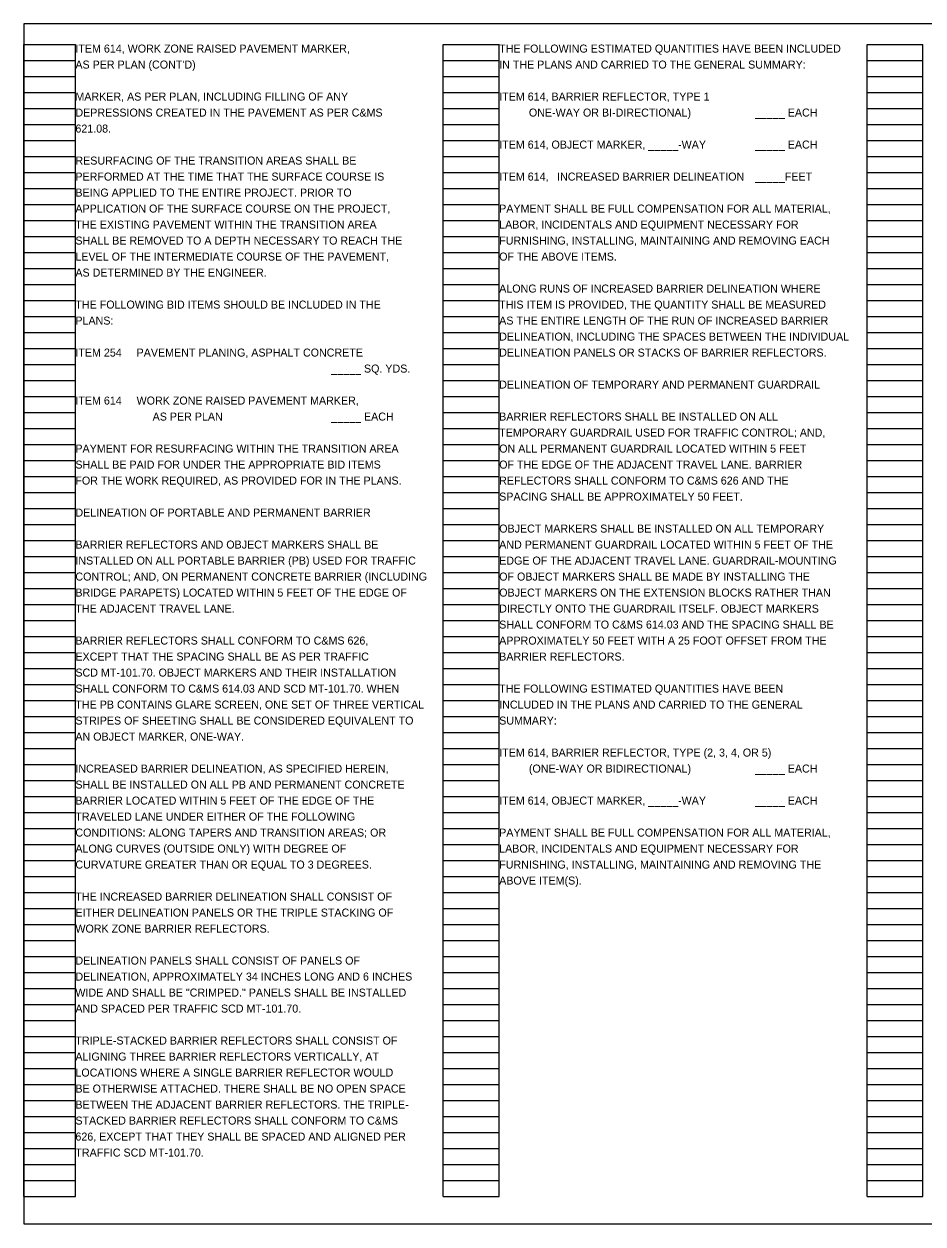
# Model space of a CAD drawing. Extents: x -34 to 2132911, y 0 to 658646.
# Drawn here: x 103.5 to 119.24, y 0.5 to 21.5 of the extents above; entities that cross this region are included whole.
import ezdxf

# ---------------------------------------------------------------- set-up
doc = ezdxf.new("R2010")
doc.units = 0
for name, color, linetype in [('SC_Scratch1', 7, 'Continuous'), ('SH_Data', 7, 'Continuous'), ('SH_Text', 7, 'Continuous')]:
    doc.layers.add(name, color=color, linetype=linetype)

msp = doc.modelspace()

# ---------------------------------------------------------------- linework, layer by layer
at = {"layer": 'SC_Scratch1'}
msp.add_lwpolyline([(103.5, 0.5), (134, 0.5), (134, 21.5), (103.5, 21.5)], close=True, dxfattribs=at)
at = {"layer": 'SH_Data'}
for p, q in [((103.5, 0.98), (103.5, 21.14)), ((103.5, 21.14), (104.4, 21.14)), ((104.4, 0.98), (104.4, 21.14)), ((110.84, 0.98), (110.84, 21.14)), ((110.84, 21.14), (111.82, 21.14)), ((111.82, 0.98), (111.82, 21.14)), ((118.26, 0.98), (118.26, 21.14)), ((118.26, 21.14), (119.24, 21.14)), ((119.24, 0.98), (119.24, 21.14)), ((103.5, 20.86), (104.4, 20.86)), ((110.84, 20.86), (111.82, 20.86)), ((118.26, 20.86), (119.24, 20.86)), ((103.5, 20.58), (104.4, 20.58)), ((110.84, 20.58), (111.82, 20.58)), ((118.26, 20.58), (119.24, 20.58)), ((103.5, 20.3), (104.4, 20.3)), ((110.84, 20.3), (111.82, 20.3)), ((118.26, 20.3), (119.24, 20.3)), ((103.5, 20.02), (104.4, 20.02)), ((110.84, 20.02), (111.82, 20.02)), ((118.26, 20.02), (119.24, 20.02)), ((103.5, 19.74), (104.4, 19.74)), ((110.84, 19.74), (111.82, 19.74)), ((118.26, 19.74), (119.24, 19.74)), ((103.5, 19.46), (104.4, 19.46)), ((110.84, 19.46), (111.82, 19.46)), ((118.26, 19.46), (119.24, 19.46)), ((103.5, 19.18), (104.4, 19.18)), ((110.84, 19.18), (111.82, 19.18)), ((118.26, 19.18), (119.24, 19.18)), ((103.5, 18.9), (104.4, 18.9)), ((110.84, 18.9), (111.82, 18.9)), ((118.26, 18.9), (119.24, 18.9)), ((103.5, 18.62), (104.4, 18.62)), ((110.84, 18.62), (111.82, 18.62)), ((118.26, 18.62), (119.24, 18.62)), ((103.5, 18.34), (104.4, 18.34)), ((110.84, 18.34), (111.82, 18.34)), ((118.26, 18.34), (119.24, 18.34)), ((103.5, 18.06), (104.4, 18.06)), ((110.84, 18.06), (111.82, 18.06)), ((118.26, 18.06), (119.24, 18.06)), ((103.5, 17.78), (104.4, 17.78)), ((110.84, 17.78), (111.82, 17.78)), ((118.26, 17.78), (119.24, 17.78)), ((103.5, 17.5), (104.4, 17.5)), ((110.84, 17.5), (111.82, 17.5)), ((118.26, 17.5), (119.24, 17.5)), ((103.5, 17.22), (104.4, 17.22)), ((110.84, 17.22), (111.82, 17.22)), ((118.26, 17.22), (119.24, 17.22)), ((103.5, 16.94), (104.4, 16.94)), ((110.84, 16.94), (111.82, 16.94)), ((118.26, 16.94), (119.24, 16.94)), ((103.5, 16.66), (104.4, 16.66)), ((110.84, 16.66), (111.82, 16.66)), ((118.26, 16.66), (119.24, 16.66)), ((103.5, 16.38), (104.4, 16.38)), ((110.84, 16.38), (111.82, 16.38)), ((118.26, 16.38), (119.24, 16.38)), ((103.5, 16.1), (104.4, 16.1)), ((110.84, 16.1), (111.82, 16.1)), ((118.26, 16.1), (119.24, 16.1)), ((103.5, 15.82), (104.4, 15.82)), ((110.84, 15.82), (111.82, 15.82)), ((118.26, 15.82), (119.24, 15.82)), ((103.5, 15.54), (104.4, 15.54)), ((110.84, 15.54), (111.82, 15.54)), ((118.26, 15.54), (119.24, 15.54)), ((103.5, 15.26), (104.4, 15.26)), ((110.84, 15.26), (111.82, 15.26)), ((118.26, 15.26), (119.24, 15.26)), ((103.5, 14.98), (104.4, 14.98)), ((110.84, 14.98), (111.82, 14.98)), ((118.26, 14.98), (119.24, 14.98)), ((103.5, 14.7), (104.4, 14.7)), ((110.84, 14.7), (111.82, 14.7)), ((118.26, 14.7), (119.24, 14.7)), ((103.5, 14.42), (104.4, 14.42)), ((110.84, 14.42), (111.82, 14.42)), ((118.26, 14.42), (119.24, 14.42)), ((103.5, 14.14), (104.4, 14.14)), ((110.84, 14.14), (111.82, 14.14)), ((118.26, 14.14), (119.24, 14.14)), ((103.5, 13.86), (104.4, 13.86)), ((110.84, 13.86), (111.82, 13.86)), ((118.26, 13.86), (119.24, 13.86)), ((103.5, 13.58), (104.4, 13.58)), ((110.84, 13.58), (111.82, 13.58)), ((118.26, 13.58), (119.24, 13.58)), ((103.5, 13.3), (104.4, 13.3)), ((110.84, 13.3), (111.82, 13.3)), ((118.26, 13.3), (119.24, 13.3)), ((103.5, 13.02), (104.4, 13.02)), ((110.84, 13.02), (111.82, 13.02)), ((118.26, 13.02), (119.24, 13.02)), ((103.5, 12.74), (104.4, 12.74)), ((110.84, 12.74), (111.82, 12.74)), ((118.26, 12.74), (119.24, 12.74)), ((103.5, 12.46), (104.4, 12.46)), ((110.84, 12.46), (111.82, 12.46)), ((118.26, 12.46), (119.24, 12.46)), ((103.5, 12.18), (104.4, 12.18)), ((110.84, 12.18), (111.82, 12.18)), ((118.26, 12.18), (119.24, 12.18)), ((103.5, 11.9), (104.4, 11.9)), ((110.84, 11.9), (111.82, 11.9)), ((118.26, 11.9), (119.24, 11.9)), ((103.5, 11.62), (104.4, 11.62)), ((110.84, 11.62), (111.82, 11.62)), ((118.26, 11.62), (119.24, 11.62)), ((103.5, 11.34), (104.4, 11.34)), ((110.84, 11.34), (111.82, 11.34)), ((118.26, 11.34), (119.24, 11.34)), ((103.5, 11.06), (104.4, 11.06)), ((110.84, 11.06), (111.82, 11.06)), ((118.26, 11.06), (119.24, 11.06)), ((103.5, 10.78), (104.4, 10.78)), ((110.84, 10.78), (111.82, 10.78)), ((118.26, 10.78), (119.24, 10.78)), ((103.5, 10.5), (104.4, 10.5)), ((110.84, 10.5), (111.82, 10.5)), ((118.26, 10.5), (119.24, 10.5)), ((103.5, 10.22), (104.4, 10.22)), ((110.84, 10.22), (111.82, 10.22)), ((118.26, 10.22), (119.24, 10.22)), ((103.5, 9.94), (104.4, 9.94)), ((110.84, 9.94), (111.82, 9.94)), ((118.26, 9.94), (119.24, 9.94)), ((103.5, 9.66), (104.4, 9.66)), ((110.84, 9.66), (111.82, 9.66)), ((118.26, 9.66), (119.24, 9.66)), ((103.5, 9.38), (104.4, 9.38)), ((110.84, 9.38), (111.82, 9.38)), ((118.26, 9.38), (119.24, 9.38)), ((103.5, 9.1), (104.4, 9.1)), ((110.84, 9.1), (111.82, 9.1)), ((118.26, 9.1), (119.24, 9.1)), ((103.5, 8.82), (104.4, 8.82)), ((110.84, 8.82), (111.82, 8.82)), ((118.26, 8.82), (119.24, 8.82)), ((103.5, 8.54), (104.4, 8.54)), ((110.84, 8.54), (111.82, 8.54)), ((118.26, 8.54), (119.24, 8.54)), ((103.5, 8.26), (104.4, 8.26)), ((110.84, 8.26), (111.82, 8.26)), ((118.26, 8.26), (119.24, 8.26)), ((103.5, 7.98), (104.4, 7.98)), ((110.84, 7.98), (111.82, 7.98)), ((118.26, 7.98), (119.24, 7.98)), ((103.5, 7.7), (104.4, 7.7)), ((110.84, 7.7), (111.82, 7.7)), ((118.26, 7.7), (119.24, 7.7)), ((103.5, 7.42), (104.4, 7.42)), ((110.84, 7.42), (111.82, 7.42)), ((118.26, 7.42), (119.24, 7.42)), ((103.5, 7.14), (104.4, 7.14)), ((110.84, 7.14), (111.82, 7.14)), ((118.26, 7.14), (119.24, 7.14)), ((103.5, 6.86), (104.4, 6.86)), ((110.84, 6.86), (111.82, 6.86)), ((118.26, 6.86), (119.24, 6.86)), ((103.5, 6.58), (104.4, 6.58)), ((110.84, 6.58), (111.82, 6.58)), ((118.26, 6.58), (119.24, 6.58)), ((103.5, 6.3), (104.4, 6.3)), ((110.84, 6.3), (111.82, 6.3)), ((118.26, 6.3), (119.24, 6.3)), ((103.5, 6.02), (104.4, 6.02)), ((110.84, 6.02), (111.82, 6.02)), ((118.26, 6.02), (119.24, 6.02)), ((103.5, 5.74), (104.4, 5.74)), ((110.84, 5.74), (111.82, 5.74)), ((118.26, 5.74), (119.24, 5.74)), ((103.5, 5.46), (104.4, 5.46)), ((110.84, 5.46), (111.82, 5.46)), ((118.26, 5.46), (119.24, 5.46)), ((103.5, 5.18), (104.4, 5.18)), ((110.84, 5.18), (111.82, 5.18)), ((118.26, 5.18), (119.24, 5.18)), ((103.5, 4.9), (104.4, 4.9)), ((110.84, 4.9), (111.82, 4.9)), ((118.26, 4.9), (119.24, 4.9)), ((103.5, 4.62), (104.4, 4.62)), ((110.84, 4.62), (111.82, 4.62)), ((118.26, 4.62), (119.24, 4.62)), ((103.5, 4.34), (104.4, 4.34)), ((110.84, 4.34), (111.82, 4.34)), ((118.26, 4.34), (119.24, 4.34)), ((103.5, 4.06), (104.4, 4.06)), ((110.84, 4.06), (111.82, 4.06)), ((118.26, 4.06), (119.24, 4.06)), ((103.5, 3.78), (104.4, 3.78)), ((110.84, 3.78), (111.82, 3.78)), ((118.26, 3.78), (119.24, 3.78)), ((103.5, 3.5), (104.4, 3.5)), ((110.84, 3.5), (111.82, 3.5)), ((118.26, 3.5), (119.24, 3.5)), ((103.5, 3.22), (104.4, 3.22)), ((110.84, 3.22), (111.82, 3.22)), ((118.26, 3.22), (119.24, 3.22)), ((103.5, 2.94), (104.4, 2.94)), ((110.84, 2.94), (111.82, 2.94)), ((118.26, 2.94), (119.24, 2.94)), ((103.5, 2.66), (104.4, 2.66)), ((110.84, 2.66), (111.82, 2.66)), ((118.26, 2.66), (119.24, 2.66)), ((103.5, 2.38), (104.4, 2.38)), ((110.84, 2.38), (111.82, 2.38)), ((118.26, 2.38), (119.24, 2.38)), ((103.5, 2.1), (104.4, 2.1)), ((110.84, 2.1), (111.82, 2.1)), ((118.26, 2.1), (119.24, 2.1)), ((103.5, 1.82), (104.4, 1.82)), ((110.84, 1.82), (111.82, 1.82)), ((118.26, 1.82), (119.24, 1.82)), ((103.5, 1.54), (104.4, 1.54)), ((110.84, 1.54), (111.82, 1.54)), ((118.26, 1.54), (119.24, 1.54)), ((103.5, 1.26), (104.4, 1.26)), ((110.84, 1.26), (111.82, 1.26)), ((118.26, 1.26), (119.24, 1.26)), ((103.5, 0.98), (104.4, 0.98)), ((110.84, 0.98), (111.82, 0.98)), ((118.26, 0.98), (119.24, 0.98))]:
    msp.add_line(p, q, dxfattribs=at)

# ---------------------------------------------------------------- texts
at = {"layer": 'SH_Text'}
for s, p in [('ITEM 614, WORK ZONE RAISED PAVEMENT MARKER,', (104.4, 21)), ('THE FOLLOWING ESTIMATED QUANTITIES HAVE BEEN INCLUDED', (111.82, 21)), ("AS PER PLAN (CONT'D) ", (104.4, 20.72)), ('IN THE PLANS AND CARRIED TO THE GENERAL SUMMARY:', (111.82, 20.72)), ('MARKER, AS PER PLAN, INCLUDING FILLING OF ANY', (104.4, 20.16)), ('ITEM 614, BARRIER REFLECTOR, TYPE 1', (111.82, 20.16)), ('DEPRESSIONS CREATED IN THE PAVEMENT AS PER C&MS', (104.4, 19.88)), ('          ONE-WAY OR BI-DIRECTIONAL)         ', (111.82, 19.88)), ('_____ EACH', (116.3, 19.88)), ('621.08.', (104.4, 19.6)), ('ITEM 614, OBJECT MARKER, _____-WAY     ', (111.82, 19.32)), ('_____ EACH', (116.3, 19.32)), ('RESURFACING OF THE TRANSITION AREAS SHALL BE', (104.4, 19.04)), ('PERFORMED AT THE TIME THAT THE SURFACE COURSE IS', (104.4, 18.76)), ('ITEM 614, ', (111.82, 18.76)), ('INCREASED BARRIER DELINEATION', (112.834, 18.76)), ('_____FEET', (116.3, 18.76)), ('BEING APPLIED TO THE ENTIRE PROJECT. PRIOR TO', (104.4, 18.48)), ('APPLICATION OF THE SURFACE COURSE ON THE PROJECT,', (104.4, 18.2)), ('PAYMENT SHALL BE FULL COMPENSATION FOR ALL MATERIAL,', (111.82, 18.2)), ('THE EXISTING PAVEMENT WITHIN THE TRANSITION AREA', (104.4, 17.92)), ('LABOR, INCIDENTALS AND EQUIPMENT NECESSARY FOR', (111.82, 17.92)), ('SHALL BE REMOVED TO A DEPTH NECESSARY TO REACH THE', (104.4, 17.64)), ('FURNISHING, INSTALLING, MAINTAINING AND REMOVING EACH', (111.82, 17.64)), ('LEVEL OF THE INTERMEDIATE COURSE OF THE PAVEMENT,', (104.4, 17.36)), ('OF THE ABOVE ITEMS.', (111.82, 17.36)), ('AS DETERMINED BY THE ENGINEER.', (104.4, 17.08)), ('ALONG RUNS OF INCREASED BARRIER DELINEATION WHERE', (111.82, 16.8)), ('THE FOLLOWING BID ITEMS SHOULD BE INCLUDED IN THE', (104.4, 16.52)), ('THIS ITEM IS PROVIDED, THE QUANTITY SHALL BE MEASURED', (111.82, 16.52)), ('PLANS:', (104.4, 16.24)), ('AS THE ENTIRE LENGTH OF THE RUN OF INCREASED BARRIER', (111.82, 16.24)), ('DELINEATION, INCLUDING THE SPACES BETWEEN THE INDIVIDUAL', (111.82, 15.96)), ('ITEM 254     PAVEMENT PLANING, ASPHALT CONCRETE', (104.4, 15.68)), ('DELINEATION PANELS OR STACKS OF BARRIER REFLECTORS.', (111.82, 15.68)), ('_____ SQ. YDS.', (108.88, 15.4)), ('DELINEATION OF TEMPORARY AND PERMANENT GUARDRAIL', (111.82, 15.12)), ('ITEM 614     WORK ZONE RAISED PAVEMENT MARKER,', (104.4, 14.84)), ('                          AS PER PLAN     ', (104.4, 14.56)), ('_____ EACH', (108.88, 14.56)), ('BARRIER REFLECTORS SHALL BE INSTALLED ON ALL', (111.82, 14.56)), ('TEMPORARY GUARDRAIL USED FOR TRAFFIC CONTROL; AND,', (111.82, 14.28)), ('PAYMENT FOR RESURFACING WITHIN THE TRANSITION AREA', (104.4, 14)), ('ON ALL PERMANENT GUARDRAIL LOCATED WITHIN 5 FEET', (111.82, 14)), ('SHALL BE PAID FOR UNDER THE APPROPRIATE BID ITEMS', (104.4, 13.72)), ('OF THE EDGE OF THE ADJACENT TRAVEL LANE. BARRIER', (111.82, 13.72)), ('FOR THE WORK REQUIRED, AS PROVIDED FOR IN THE PLANS.', (104.4, 13.44)), ('REFLECTORS SHALL CONFORM TO C&MS 626 AND THE', (111.82, 13.44)), ('SPACING SHALL BE APPROXIMATELY 50 FEET.', (111.82, 13.16)), ('DELINEATION OF PORTABLE AND PERMANENT BARRIER', (104.4, 12.88)), ('OBJECT MARKERS SHALL BE INSTALLED ON ALL TEMPORARY', (111.82, 12.6)), ('BARRIER REFLECTORS AND OBJECT MARKERS SHALL BE', (104.4, 12.32)), ('AND PERMANENT GUARDRAIL LOCATED WITHIN 5 FEET OF THE', (111.82, 12.32)), ('INSTALLED ON ALL PORTABLE BARRIER (PB) USED FOR TRAFFIC', (104.4, 12.04)), ('EDGE OF THE ADJACENT TRAVEL LANE. GUARDRAIL-MOUNTING', (111.82, 12.04)), ('CONTROL; AND, ON PERMANENT CONCRETE BARRIER (INCLUDING', (104.4, 11.76)), ('OF OBJECT MARKERS SHALL BE MADE BY INSTALLING THE', (111.82, 11.76)), ('BRIDGE PARAPETS) LOCATED WITHIN 5 FEET OF THE EDGE OF', (104.4, 11.48)), ('OBJECT MARKERS ON THE EXTENSION BLOCKS RATHER THAN', (111.82, 11.48)), ('THE ADJACENT TRAVEL LANE.', (104.4, 11.2)), ('DIRECTLY ONTO THE GUARDRAIL ITSELF. OBJECT MARKERS', (111.82, 11.2)), ('SHALL CONFORM TO C&MS 614.03 AND THE SPACING SHALL BE', (111.82, 10.92)), ('BARRIER REFLECTORS SHALL CONFORM TO C&MS 626,', (104.4, 10.64)), ('APPROXIMATELY 50 FEET WITH A 25 FOOT OFFSET FROM THE', (111.82, 10.64)), ('EXCEPT THAT THE SPACING SHALL BE AS PER TRAFFIC', (104.4, 10.36)), ('BARRIER REFLECTORS.', (111.82, 10.36)), ('SCD MT-101.70. OBJECT MARKERS AND THEIR INSTALLATION', (104.4, 10.08)), ('SHALL CONFORM TO C&MS 614.03 AND SCD MT-101.70. WHEN', (104.4, 9.8)), ('THE FOLLOWING ESTIMATED QUANTITIES HAVE BEEN', (111.82, 9.8)), ('THE PB CONTAINS GLARE SCREEN, ONE SET OF THREE VERTICAL', (104.4, 9.52)), ('INCLUDED IN THE PLANS AND CARRIED TO THE GENERAL', (111.82, 9.52)), ('STRIPES OF SHEETING SHALL BE CONSIDERED EQUIVALENT TO', (104.4, 9.24)), ('SUMMARY:', (111.82, 9.24)), ('AN OBJECT MARKER, ONE-WAY.', (104.4, 8.96)), ('ITEM 614, BARRIER REFLECTOR, TYPE (2, 3, 4, OR 5)', (111.82, 8.68)), ('INCREASED BARRIER DELINEATION, AS SPECIFIED HEREIN,', (104.4, 8.4)), ('          (ONE-WAY OR BIDIRECTIONAL)     ', (111.82, 8.4)), ('_____ EACH', (116.3, 8.4)), ('SHALL BE INSTALLED ON ALL PB AND PERMANENT CONCRETE', (104.4, 8.12)), ('BARRIER LOCATED WITHIN 5 FEET OF THE EDGE OF THE', (104.4, 7.84)), ('ITEM 614, OBJECT MARKER, _____-WAY      ', (111.82, 7.84)), ('_____ EACH', (116.3, 7.84)), ('TRAVELED LANE UNDER EITHER OF THE FOLLOWING', (104.4, 7.56)), ('CONDITIONS: ALONG TAPERS AND TRANSITION AREAS; OR', (104.4, 7.28)), ('PAYMENT SHALL BE FULL COMPENSATION FOR ALL MATERIAL,', (111.82, 7.28)), ('ALONG CURVES (OUTSIDE ONLY) WITH DEGREE OF', (104.4, 7)), ('LABOR, INCIDENTALS AND EQUIPMENT NECESSARY FOR', (111.82, 7)), ('CURVATURE GREATER THAN OR EQUAL TO 3 DEGREES.', (104.4, 6.72)), ('FURNISHING, INSTALLING, MAINTAINING AND REMOVING THE', (111.82, 6.72)), ('ABOVE ITEM(S).', (111.82, 6.44)), ('THE INCREASED BARRIER DELINEATION SHALL CONSIST OF', (104.4, 6.16)), ('EITHER DELINEATION PANELS OR THE TRIPLE STACKING OF', (104.4, 5.88)), ('WORK ZONE BARRIER REFLECTORS.', (104.4, 5.6)), ('DELINEATION PANELS SHALL CONSIST OF PANELS OF', (104.4, 5.04)), ('DELINEATION, APPROXIMATELY 34 INCHES LONG AND 6 INCHES', (104.4, 4.76)), ('WIDE AND SHALL BE "CRIMPED." PANELS SHALL BE INSTALLED', (104.4, 4.48)), ('AND SPACED PER TRAFFIC SCD MT-101.70.', (104.4, 4.2)), ('TRIPLE-STACKED BARRIER REFLECTORS SHALL CONSIST OF', (104.4, 3.64)), ('ALIGNING THREE BARRIER REFLECTORS VERTICALLY, AT', (104.4, 3.36)), ('LOCATIONS WHERE A SINGLE BARRIER REFLECTOR WOULD', (104.4, 3.08)), ('BE OTHERWISE ATTACHED. THERE SHALL BE NO OPEN SPACE', (104.4, 2.8)), ('BETWEEN THE ADJACENT BARRIER REFLECTORS. THE TRIPLE-', (104.4, 2.52)), ('STACKED BARRIER REFLECTORS SHALL CONFORM TO C&MS', (104.4, 2.24)), ('626, EXCEPT THAT THEY SHALL BE SPACED AND ALIGNED PER', (104.4, 1.96)), ('TRAFFIC SCD MT-101.70.', (104.4, 1.68))]:
    msp.add_text(s, height=0.14, dxfattribs=at).set_placement(p)

doc.saveas('drawing.dxf')
